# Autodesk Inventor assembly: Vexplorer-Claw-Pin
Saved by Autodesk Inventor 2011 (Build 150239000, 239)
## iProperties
Created: 2007-10
Part Number: Vexplorer-Claw-Pin
Document SubType Name: Assembly
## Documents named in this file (3)
- C:\Data Folder\VEX 2011\Inventor Datasets\Unit 12\Components\Vexplorer-Claw-Pin.iam
- C:\Data Folder\VEX 2011\Inventor Datasets\Unit 12\Components\NONED.ipt
- C:\Data Folder\VEX 2011\Inventor Datasets\Unit 12\Components\NONEE.ipt
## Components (2 placed, 2 different names)
1. NONED
2. NONEE
